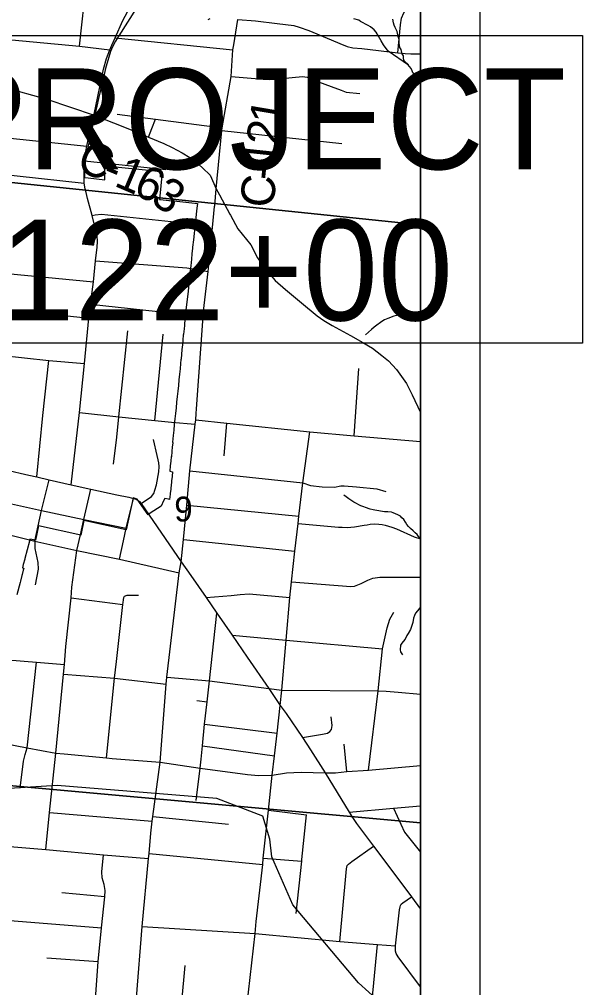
# Model space of a CAD drawing. Extents: x 0 to 34, y 0 to 22.
# Drawn here: x 8.223 to 9.174, y 18.91 to 20.543 of the extents above; entities that cross this region are included whole.
import ezdxf

# ---------------------------------------------------------------- set-up
doc = ezdxf.new("R2010")
doc.units = 0
for name, color, linetype in [('GM_X_City_Street', 7, 'Continuous'), ('GM_X_Corporation', 7, 'Continuous'), ('GM_X_County_Road', 7, 'Continuous'), ('GM_X_County_Road_Text', 7, 'Continuous'), ('GM_X_Minor_River', 7, 'Continuous'), ('GM_X_Rail_Line', 7, 'Continuous'), ('GM_X_Section_Text', 7, 'Continuous'), ('GM_X_Township_Road', 7, 'Continuous'), ('SH_Data', 7, 'Continuous'), ('SH_Masking', 7, 'Continuous'), ('SH_Text', 7, 'Continuous')]:
    doc.layers.add(name, color=color, linetype=linetype)

msp = doc.modelspace()

# ---------------------------------------------------------------- linework, layer by layer
at = {"layer": 'GM_X_City_Street'}
for p, q in [((8.3245, 20.4975), (8.3324, 20.5696)), ((8.0501, 20.3585), (8.3368, 20.329)), ((8.3516, 20.1359), (8.5054, 20.1236)), ((8.5054, 20.1236), (8.5413, 20.1178)), ((8.2021, 20.114), (8.3479, 20.1001)), ((8.1964, 20.0545), (8.34, 20.0392)), ((8.3432, 20.0627), (8.4985, 20.0459)), ((8.4985, 20.0459), (8.533, 20.0415)), ((8.4516, 19.8662), (8.4658, 20.0117)), ((8.7877, 19.8404), (8.796, 19.9541)), ((8.4796, 19.8637), (8.5194, 19.8601)), ((8.5684, 19.8069), (8.5728, 19.862)), ((8.5053, 19.7233), (8.6948, 19.7048)), ((8.3317, 19.6992), (8.403, 19.6848)), ((8.4997, 19.6658), (8.688, 19.646)), ((8.3102, 19.5673), (8.3976, 19.556)), ((8.5222, 19.394), (8.5396, 19.3918)), ((8.5351, 19.3543), (8.6578, 19.339)), ((8.5317, 19.3178), (8.6532, 19.3011)), ((8.7756, 19.2743), (8.7711, 19.3204)), ((8.521, 19.2253), (8.5283, 19.28)), ((8.2739, 19.2053), (8.4471, 19.1906)), ((8.6432, 19.209), (8.7077, 19.2014)), ((8.4479, 19.1983), (8.5759, 19.1857)), ((8.4417, 19.1363), (8.6337, 19.1175)), ((8.6346, 19.1281), (8.6995, 19.1232)), ((8.3671, 19.0633), (8.2945, 19.0699)), ((8.1298, 19.0296), (8.3614, 19.0106)), ((8.8182, 18.8888), (8.8272, 18.9828)), ((8.2695, 18.9604), (8.3561, 18.9539)), ((8.4972, 18.886), (8.5029, 18.9474))]:
    msp.add_line(p, q, dxfattribs=at)
for points in [[(8.1673, 20.5122), (8.3245, 20.4975), (8.3757, 20.4915)], [(8.0437, 20.2985), (8.1053, 20.2918), (8.1602, 20.2855), (8.2192, 20.279), (8.3322, 20.2666)], [(8.3456, 20.2119), (8.3507, 20.2134), (8.3614, 20.2146), (8.4899, 20.2008)], [(7.8797, 20.0085), (7.9555, 20.0012), (8.0027, 19.9961), (8.0143, 19.995), (8.0747, 19.9886), (8.0831, 19.9878), (8.1298, 19.9828), (8.1423, 19.9813), (8.1899, 19.9763), (8.2727, 19.9678), (8.333, 19.9627)], [(8.382, 19.7925), (8.3872, 19.8384), (8.391, 19.8724), (8.406, 20.0173)], [(8.2523, 19.7711), (8.2626, 19.8747), (8.2727, 19.9678)], [(8.3244, 19.8797), (8.391, 19.8724), (8.4516, 19.8662), (8.4796, 19.8637)], [(8.6633, 19.386), (8.6659, 19.4115), (8.6734, 19.4958), (8.6791, 19.5679), (8.6821, 19.5944), (8.688, 19.646), (8.6934, 19.6925), (8.6948, 19.7048), (8.7013, 19.7612), (8.713, 19.8474)], [(8.4285, 19.7262), (8.4457, 19.7383), (8.4496, 19.7432), (8.4516, 19.749), (8.4541, 19.7576), (8.4584, 19.7797), (8.4589, 19.789), (8.4582, 19.7949), (8.457, 19.8), (8.4553, 19.8073), (8.4493, 19.8343)], [(8.5104, 19.7814), (8.6855, 19.7632), (8.7013, 19.7612), (8.7144, 19.757), (8.7339, 19.7545), (8.755, 19.7542), (8.7652, 19.756), (8.7713, 19.7564), (8.7917, 19.7543), (8.8262, 19.7514), (8.8416, 19.7464)], [(8.0439, 19.7651), (8.1515, 19.7403), (8.1946, 19.7292), (8.2605, 19.7148), (8.3317, 19.6992)], [(8.2488, 19.6631), (8.2605, 19.7148), (8.2733, 19.7661)], [(8.3259, 19.6734), (8.3317, 19.6992), (8.3435, 19.7504)], [(8.3921, 19.6326), (8.3988, 19.6633), (8.403, 19.6848), (8.4155, 19.7351)], [(8.0243, 19.7154), (8.1405, 19.6886), (8.1837, 19.679), (8.2356, 19.6661)], [(8.6934, 19.6925), (8.7613, 19.6863), (8.7676, 19.6862), (8.776, 19.686), (8.7885, 19.6872), (8.8048, 19.6899), (8.81, 19.6906), (8.8147, 19.6916), (8.822, 19.6922), (8.8295, 19.6914), (8.8351, 19.6908), (8.8405, 19.69), (8.8514, 19.6867), (8.8594, 19.6838), (8.8893, 19.6701), (8.9, 19.6669)], [(8.2356, 19.6661), (8.2488, 19.6631), (8.3201, 19.647), (8.3921, 19.6326), (8.4923, 19.6097)], [(8.2488, 19.6631), (8.2489, 19.6504), (8.2538, 19.6271), (8.2544, 19.6157), (8.2494, 19.5894)], [(8.2678, 19.1429), (8.2739, 19.2053), (8.2845, 19.3053), (8.2971, 19.4388), (8.2988, 19.455), (8.3012, 19.4853), (8.3102, 19.5673), (8.3117, 19.5852), (8.3201, 19.647), (8.3259, 19.6734)], [(8.6821, 19.5944), (8.7821, 19.5865), (8.7887, 19.587), (8.7996, 19.5913), (8.8109, 19.5971), (8.8193, 19.6005), (8.8311, 19.6021), (8.9, 19.6023)], [(8.3976, 19.556), (8.3979, 19.5597), (8.3985, 19.5641), (8.3993, 19.5676), (8.4005, 19.5701), (8.4049, 19.5717), (8.4118, 19.5718), (8.4242, 19.5718)], [(8.5384, 19.5677), (8.5801, 19.5714), (8.5957, 19.573), (8.6109, 19.5742), (8.6791, 19.5679)], [(8.3697, 19.2973), (8.3837, 19.4319), (8.3866, 19.4602), (8.3976, 19.556)], [(8.5283, 19.28), (8.5295, 19.2955), (8.5317, 19.3178), (8.5351, 19.3543), (8.5396, 19.3918), (8.5438, 19.4274), (8.5564, 19.5412)], [(8.812, 19.2765), (8.8282, 19.4107), (8.836, 19.4814), (8.8437, 19.5166), (8.848, 19.5312), (8.8549, 19.5429)], [(8.5818, 19.5043), (8.6734, 19.4958), (8.836, 19.4814)], [(8.2035, 19.463), (8.252, 19.459), (8.2988, 19.455)], [(8.2241, 19.2463), (8.2297, 19.2919), (8.2327, 19.3033), (8.2363, 19.3146), (8.252, 19.459)], [(8.2971, 19.4388), (8.3837, 19.4319), (8.4707, 19.4216)], [(8.4719, 19.4333), (8.5438, 19.4274), (8.6437, 19.4144), (8.6659, 19.4115), (8.8282, 19.4107), (8.8418, 19.41), (8.8623, 19.4082), (8.9, 19.4047)], [(8.7009, 19.3318), (8.7346, 19.3373), (8.7432, 19.3393), (8.7468, 19.3421), (8.7497, 19.3455), (8.7509, 19.3519), (8.7492, 19.3667)], [(8.7793, 19.206), (8.8541, 19.2124), (8.9, 19.2165)], [(8.8541, 19.2124), (8.873, 19.1722), (8.9, 19.1385)], [(8.6903, 19.0347), (8.6995, 19.1232), (8.6998, 19.126), (8.7077, 19.2014)], [(7.9429, 19.17), (8.0783, 19.1589), (8.1459, 19.1531), (8.2678, 19.1429), (8.365, 19.1341), (8.4409, 19.1278)], [(8.764, 18.9877), (8.7747, 19.1039), (8.7752, 19.11), (8.7759, 19.1157), (8.7781, 19.1181), (8.7841, 19.1229), (8.8205, 19.1487)], [(8.334, 18.785), (8.3377, 18.7878), (8.3408, 18.7934), (8.3415, 18.7989), (8.3438, 18.8296), (8.3518, 18.8983), (8.3561, 18.9539), (8.3614, 19.0106), (8.3671, 19.0633), (8.3678, 19.0737), (8.3662, 19.0839), (8.3627, 19.095), (8.3619, 19.105), (8.365, 19.1341)], [(8.9, 18.9112), (8.8621, 18.9616), (8.8587, 18.9676), (8.8578, 18.9712), (8.8575, 18.9753), (8.8579, 18.9805), (8.8646, 19.0409), (8.8654, 19.0461), (8.866, 19.0485), (8.8672, 19.0505), (8.87, 19.0531), (8.8849, 19.0628)], [(8.4299, 19.0133), (8.6208, 19.0011), (8.764, 18.9877), (8.8272, 18.9828), (8.8579, 18.9805)]]:
    msp.add_lwpolyline(points, dxfattribs=at)
at = {"layer": 'GM_X_Corporation'}
for points in [[(8.9, 14.3814), (8.9, 20.9), (2.1, 20.9)], [(8.9, 17.1766), (8.9, 20.9), (4.0645, 20.9), (4.0111, 20.3696), (4.0006, 20.2658), (3.9936, 20.1954), (3.918, 19.4442), (3.8667, 18.9339), (3.8234, 18.553), (3.8126, 18.3974), (3.8023, 18.3182), (3.7454, 17.7286)], [(8.4199, 20.5613), (8.3907, 20.515), (8.3854, 20.5063), (8.38, 20.4966), (8.3769, 20.4885), (8.3692, 20.4639), (8.3679, 20.4578), (8.3648, 20.4444), (8.3639, 20.4406), (8.3581, 20.4161), (8.3578, 20.4147), (8.3525, 20.3916), (8.3504, 20.3823), (8.34, 20.3337), (8.3396, 20.332), (8.3381, 20.3251), (8.3379, 20.3245), (8.3343, 20.3085), (8.3332, 20.3002), (8.3329, 20.2946), (8.3327, 20.2881), (8.333, 20.276), (8.339, 20.2754), (8.3672, 20.2725), (8.3672, 20.2791), (8.3672, 20.2817), (8.3672, 20.2961), (8.3729, 20.2955), (8.436, 20.2889), (8.4472, 20.2877), (8.464, 20.286), (8.4617, 20.2619), (8.4595, 20.239), (8.461, 20.2389), (8.475, 20.2374), (8.4765, 20.2372), (8.4889, 20.236), (8.504, 20.2344), (8.5142, 20.2334), (8.5234, 20.2322), (8.5226, 20.2245), (8.5203, 20.2036), (8.5196, 20.198), (8.5167, 20.1713), (8.5153, 20.1586), (8.5151, 20.1571), (8.5142, 20.1477), (8.5132, 20.1383), (8.512, 20.1272), (8.5108, 20.1159), (8.5095, 20.1032), (8.5075, 20.0844), (8.5065, 20.0749), (8.5041, 20.0529), (8.5029, 20.0416), (8.5022, 20.0342), (8.5018, 20.0305), (8.5014, 20.0267), (8.5008, 20.0211), (8.4998, 20.0117), (8.4996, 20.0102), (8.4989, 20.0026), (8.498, 19.9939), (8.4973, 19.9862), (8.4957, 19.9699), (8.4956, 19.9696), (8.4949, 19.9622), (8.4948, 19.9615), (8.4942, 19.9549), (8.4941, 19.9537), (8.4931, 19.9443), (8.4921, 19.9349), (8.4912, 19.9255), (8.4902, 19.916), (8.4892, 19.9066), (8.4882, 19.8972), (8.4873, 19.8878), (8.4863, 19.8784), (8.4853, 19.8689), (8.4844, 19.8596), (8.4834, 19.8502), (8.4824, 19.8408), (8.4812, 19.8296), (8.4817, 19.8295), (8.4817, 19.8289), (8.481, 19.8216), (8.4804, 19.8149), (8.4804, 19.8138), (8.4797, 19.8058), (8.4796, 19.8053), (8.4791, 19.8054), (8.4784, 19.7979), (8.4776, 19.7899), (8.4767, 19.781), (8.4814, 19.78), (8.4806, 19.7725), (8.4805, 19.7711), (8.4798, 19.7649), (8.4795, 19.7619), (8.4791, 19.7579), (8.479, 19.7573), (8.4785, 19.7522), (8.4783, 19.7505), (8.4775, 19.7431), (8.4774, 19.7422), (8.4764, 19.7331), (8.4743, 19.7335), (8.4683, 19.7348), (8.4663, 19.7307), (8.462, 19.7221), (8.45, 19.714), (8.4455, 19.711), (8.4402, 19.7074), (8.4219, 19.7339), (8.4149, 19.7357), (8.4031, 19.6817), (8.3317, 19.6977), (8.3264, 19.6732), (8.2552, 19.689), (8.2499, 19.6645), (8.2407, 19.6662), (8.2398, 19.6628), (8.2322, 19.6338), (8.2319, 19.6327), (8.2295, 19.6235), (8.2281, 19.6181), (8.2306, 19.6176), (8.2294, 19.6139), (8.2277, 19.6068), (8.2271, 19.6047), (8.2247, 19.5954), (8.2243, 19.5934), (8.2188, 19.5721)]]:
    msp.add_lwpolyline(points, dxfattribs=at)
for points in [[(8.9, 20.1965), (8.9, 20.9), (8.1157, 20.9), (8.0517, 20.2839)], [(8.9, 19.1876), (8.9, 20.1965), (8.0517, 20.2839), (7.955, 19.3167), (7.9506, 19.2737)], [(8.9, 18.6915), (8.9, 19.1876), (7.9506, 19.2737), (7.8526, 18.2675), (8.8482, 18.1868)]]:
    msp.add_lwpolyline(points, close=True, dxfattribs=at)
at = {"layer": 'GM_X_County_Road'}
for p, q in [((8.5848, 20.4997), (8.5917, 20.5424)), ((8.334, 20.2569), (8.3322, 20.2666)), ((8.5525, 20.229), (8.5552, 20.2568))]:
    msp.add_line(p, q, dxfattribs=at)
for points in [[(8.3489, 20.3815), (8.3492, 20.3828), (8.3647, 20.4587), (8.3698, 20.4768), (8.3757, 20.4915), (8.3789, 20.4993), (8.3845, 20.5117), (8.3976, 20.5409), (8.4056, 20.5553), (8.4122, 20.5655)], [(8.5552, 20.2568), (8.5647, 20.3555), (8.5652, 20.3602), (8.5801, 20.4467), (8.5834, 20.4912), (8.5848, 20.4997)], [(7.8783, 20.4665), (7.8893, 20.4654), (8.198, 20.4259), (8.2071, 20.425), (8.2207, 20.4216), (8.2693, 20.4082), (8.3489, 20.3815)], [(8.3368, 20.329), (8.3394, 20.3423), (8.3489, 20.3815)], [(8.3489, 20.3815), (8.4146, 20.3552), (8.4407, 20.3442), (8.4667, 20.3335), (8.4809, 20.3266), (8.4978, 20.3178), (8.5104, 20.3098), (8.5211, 20.3018), (8.5321, 20.2922), (8.545, 20.28), (8.5552, 20.2568), (8.5608, 20.2467), (8.5783, 20.2144), (8.5792, 20.2126)], [(8.3878, 20.3829), (8.4524, 20.3746), (8.5652, 20.3602)], [(8.4407, 20.3442), (8.4466, 20.3589), (8.4524, 20.3746)], [(8.3327, 20.3041), (8.3331, 20.3108), (8.3368, 20.329)], [(8.3322, 20.2666), (8.3321, 20.2747), (8.3325, 20.2851), (8.3327, 20.3041)], [(8.3103, 19.7577), (8.3244, 19.8797), (8.333, 19.9627), (8.34, 20.0392), (8.3432, 20.0627), (8.3479, 20.1001), (8.3516, 20.1359), (8.3541, 20.1586), (8.3549, 20.1683), (8.3543, 20.1777), (8.3456, 20.2119), (8.3379, 20.2409), (8.3354, 20.251), (8.334, 20.2569)], [(8.535, 20.0602), (8.5413, 20.1178), (8.5462, 20.1628), (8.5524, 20.2271), (8.5525, 20.229)], [(8.5792, 20.2126), (8.5916, 20.1897), (8.6136, 20.1625), (8.625, 20.1409), (8.6377, 20.1224), (8.6548, 20.1026), (8.6723, 20.0871), (8.6989, 20.0646), (8.7253, 20.0429), (8.7369, 20.0348), (8.751, 20.0264), (8.7815, 20.0097), (8.8024, 19.9981), (8.8188, 19.9881), (8.8346, 19.9762), (8.846, 19.9669), (8.8593, 19.9522), (8.8761, 19.9289), (8.8859, 19.9098), (8.9, 19.88)], [(8.5214, 19.8779), (8.5221, 19.8862), (8.533, 20.0415), (8.5339, 20.0497), (8.535, 20.0602)], [(8.4959, 19.6279), (8.4997, 19.6658), (8.5053, 19.7233), (8.5104, 19.7814), (8.5194, 19.8601), (8.5205, 19.8675), (8.5214, 19.8779)], [(8.5205, 19.8675), (8.5728, 19.862), (8.713, 19.8474), (8.7877, 19.8404), (8.9, 19.831)], [(8.1998, 19.7832), (8.2388, 19.7742), (8.2523, 19.7711), (8.2733, 19.7661), (8.3103, 19.7577), (8.3435, 19.7504), (8.3876, 19.7412), (8.4077, 19.7368), (8.4155, 19.7351)], [(8.4155, 19.7351), (8.4198, 19.7337), (8.4228, 19.7321), (8.4254, 19.7295), (8.4285, 19.7262)], [(8.4285, 19.7262), (8.4959, 19.6279), (8.5122, 19.6047), (8.5384, 19.5677), (8.5564, 19.5412), (8.5818, 19.5043), (8.6075, 19.4671), (8.6437, 19.4144), (8.6633, 19.386), (8.6732, 19.3721), (8.7009, 19.3318), (8.7143, 19.311), (8.7392, 19.272), (8.7793, 19.206), (8.785, 19.1966), (8.7918, 19.1869), (8.8205, 19.1487), (8.8652, 19.0896), (8.8849, 19.0628), (8.9, 19.0421)], [(8.4088, 18.7934), (8.4206, 18.8926), (8.4299, 19.0133), (8.4409, 19.1278), (8.4417, 19.1363), (8.445, 19.1703), (8.4471, 19.1906), (8.4479, 19.1983), (8.4604, 19.2899), (8.4707, 19.4216), (8.4719, 19.4333), (8.4923, 19.6097), (8.4959, 19.6279)], [(8.5874, 18.7084), (8.6065, 18.8774), (8.6208, 19.0011), (8.6224, 19.0214), (8.6337, 19.1175), (8.6346, 19.1281), (8.6432, 19.209), (8.6497, 19.2682), (8.6532, 19.3011), (8.6578, 19.339), (8.6633, 19.386)], [(7.96, 19.3445), (8.1633, 19.325), (8.1946, 19.3219), (8.203, 19.3209), (8.2156, 19.3185), (8.2363, 19.3146), (8.2845, 19.3053), (8.2985, 19.304), (8.3697, 19.2973), (8.3797, 19.2965)], [(8.3797, 19.2965), (8.4604, 19.2899), (8.5283, 19.28), (8.6077, 19.2695), (8.6267, 19.2676), (8.6497, 19.2682), (8.674, 19.2719), (8.6986, 19.2732), (8.7392, 19.272)], [(8.7392, 19.272), (8.7565, 19.2721), (8.7756, 19.2743), (8.812, 19.2765), (8.9, 19.2845)]]:
    msp.add_lwpolyline(points, dxfattribs=at)
at = {"layer": 'GM_X_Minor_River'}
for points in [[(8.5442, 20.544), (8.5411, 20.5422)], [(8.8794, 20.4655), (8.8454, 20.4891), (8.8425, 20.493), (8.8403, 20.4961), (8.8373, 20.5), (8.8333, 20.5066), (8.829, 20.5143), (8.825, 20.5213), (8.8217, 20.5252), (8.8157, 20.5303), (8.8116, 20.5327), (8.7988, 20.5395), (8.7959, 20.5415), (8.7872, 20.544)], [(8.9, 20.4403), (8.8952, 20.4451), (8.887, 20.4529), (8.8859, 20.456), (8.8841, 20.4598), (8.8786, 20.4665), (8.8738, 20.4704), (8.8716, 20.4739), (8.871, 20.4781), (8.871, 20.4811), (8.8689, 20.485), (8.8672, 20.4923), (8.865, 20.4954), (8.8643, 20.4992), (8.864, 20.5023), (8.8638, 20.5091), (8.862, 20.5138), (8.8604, 20.5222), (8.8571, 20.5291), (8.8557, 20.533), (8.8543, 20.5368), (8.8533, 20.5433)], [(8.9, 20.0492), (8.8947, 20.0486), (8.8878, 20.0481), (8.884, 20.0478), (8.8798, 20.0475), (8.8756, 20.0469), (8.8703, 20.0463), (8.8653, 20.0453), (8.8592, 20.0435), (8.8546, 20.0421), (8.845, 20.0386), (8.8392, 20.0361), (8.8361, 20.0343), (8.8326, 20.0317), (8.8264, 20.0273), (8.8218, 20.0236), (8.8171, 20.0199), (8.8073, 20.0107)], [(8.9, 19.6671), (8.8996, 19.6676), (8.8966, 19.6708), (8.894, 19.6739), (8.8907, 19.677), (8.8877, 19.6802), (8.8829, 19.6845), (8.8796, 19.6876), (8.877, 19.6911), (8.8748, 19.695), (8.8715, 19.6993), (8.8686, 19.702), (8.866, 19.7051), (8.8619, 19.7072), (8.854, 19.7108), (8.851, 19.7117), (8.8449, 19.7122), (8.8392, 19.7124), (8.8324, 19.7133), (8.8293, 19.7138), (8.8229, 19.7151), (8.8199, 19.7156), (8.815, 19.7168), (8.8071, 19.7197), (8.804, 19.7206), (8.7992, 19.7226), (8.7958, 19.7242), (8.7917, 19.7266), (8.7875, 19.7287), (8.7838, 19.731), (8.7789, 19.7342), (8.7745, 19.7374), (8.7704, 19.7406)], [(8.9, 19.5521), (8.8987, 19.5507), (8.8947, 19.5451), (8.8912, 19.5414), (8.8896, 19.5373), (8.8883, 19.5331), (8.887, 19.5259), (8.8853, 19.5206), (8.8829, 19.5139), (8.8793, 19.5071), (8.8769, 19.5037), (8.8741, 19.4977), (8.8705, 19.4936), (8.8682, 19.4907), (8.8662, 19.4877), (8.8656, 19.4797), (8.8659, 19.4762), (8.8695, 19.4712)]]:
    msp.add_lwpolyline(points, dxfattribs=at)
at = {"layer": 'GM_X_Rail_Line'}
msp.add_lwpolyline([(8.9, 18.8237), (8.795, 18.9183), (8.6846, 19.0497), (8.6488, 19.1303), (8.6458, 19.1602), (8.6339, 19.199), (8.5563, 19.2289), (8.2864, 19.2507), (8.1872, 19.2444), (8.0986, 19.2233), (8.01, 19.2212), (7.9298, 19.2212), (7.7314, 19.2507)], dxfattribs=at)
at = {"layer": 'GM_X_Township_Road'}
for p, q in [((8.3845, 20.5117), (8.5834, 20.4912)), ((8.5647, 20.3555), (8.7672, 20.3336)), ((8.3327, 20.3041), (8.4702, 20.2897))]:
    msp.add_line(p, q, dxfattribs=at)
for points in [[(8.8614, 20.4866), (8.8663, 20.5339), (8.8678, 20.5447), (8.872, 20.5537), (8.8812, 20.5693), (8.8871, 20.5819), (8.8897, 20.5935), (8.8915, 20.6107)], [(8.5917, 20.5424), (8.6212, 20.5403), (8.6577, 20.5357), (8.6862, 20.5323), (8.6949, 20.5296), (8.7112, 20.5241), (8.7489, 20.5085), (8.7639, 20.5022)], [(8.7639, 20.5022), (8.7762, 20.4972), (8.7856, 20.4948), (8.8011, 20.4935), (8.8614, 20.4866), (8.8739, 20.4851), (8.8838, 20.4846), (8.9, 20.4846)], [(8.5801, 20.4467), (8.6345, 20.4421), (8.6455, 20.4416), (8.6603, 20.4426), (8.7009, 20.4467), (8.7085, 20.4451), (8.7213, 20.44), (8.7659, 20.4232), (8.7742, 20.4201), (8.7973, 20.418)]]:
    msp.add_lwpolyline(points, dxfattribs=at)
at = {"layer": 'SH_Data'}
for p, q in [((9, 21), (9, 14)), ((8.9, 20.9), (8.9, 14.1))]:
    msp.add_line(p, q, dxfattribs=at)
at = {"layer": 'SH_Masking'}
msp.add_lwpolyline([(7.4161, 20.5159), (9.1735, 20.5159), (9.1735, 19.9965), (7.4161, 19.9965)], close=True, dxfattribs=at)
at = {"layer": 'SH_Text'}
msp.add_lwpolyline([(7.4161, 20.5159), (9.1735, 20.5159), (9.1735, 19.9965), (7.4161, 19.9965)], close=True, dxfattribs=at)

# ---------------------------------------------------------------- texts
at = {"layer": 'GM_X_County_Road_Text'}
for s, rotation, p in [('1', 80.3272, (8.6662, 20.3618)), ('2', 82.813, (8.6619, 20.3277)), ('C', 336.9534, (8.3165, 20.2902)), ('1', 83.9872, (8.6583, 20.2932)), ('1', 336.8978, (8.3809, 20.2628)), ('-', 336.9411, (8.3595, 20.2719)), ('6', 334.8629, (8.4126, 20.2493)), ('-', 84.5648, (8.6561, 20.2701)), ('3', 324.229, (8.4419, 20.2358)), ('C', 84.7498, (8.6518, 20.2237))]:
    msp.add_text(s, height=0.0568, rotation=rotation, dxfattribs=at).set_placement(p)
at = {"layer": 'GM_X_Section_Text'}
msp.add_text('9', height=0.0419, rotation=0, dxfattribs=at).set_placement((8.4843, 19.6961))
at = {"layer": 'SH_Text'}
for s, p in [('END PROJECT', (7.5415, 20.2901)), ('STA. 122+00', (7.6213, 20.0351))]:
    msp.add_text(s, height=0.17, dxfattribs=at).set_placement(p)

doc.saveas('drawing.dxf')
